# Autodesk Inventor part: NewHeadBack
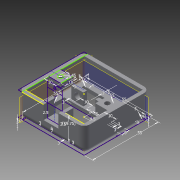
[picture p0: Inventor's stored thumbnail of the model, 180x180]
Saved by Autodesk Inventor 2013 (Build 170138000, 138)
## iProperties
Created: 2013-04
Part Number: NewHeadBack
Material: Generic
Document SubType Name: Modeling
Designer: frankenteddy
Density: 1 g/cm^3
Author: frankenteddy
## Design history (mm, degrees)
node "Blocks"
  sketch "Block1"
    geometry: L1 (49.279, 30.472)-(71.779, 30.472); L2 (71.779, 30.472)-(71.779, 18.072); L3 (71.779, 18.072)-(49.279, 18.072); L4 (49.279, 18.072)-(49.279, 30.472); L5 (49.279, 30.472)-(44.779, 30.472); L6 (44.779, 30.472)-(44.779, 18.072); L7 (44.779, 18.072)-(49.279, 18.072); L8 (49.279, 18.072)-(49.279, 30.472); L9 (71.779, 30.472)-(76.279, 30.472); L10 (76.279, 30.472)-(76.279, 18.072); L11 (76.279, 18.072)-(71.779, 18.072); L12 (71.779, 18.072)-(71.779, 30.472); L13 (44.779, 24.272)-(76.279, 24.272); L14 (60.529, 30.472)-(60.529, 18.072); L15 (47.029, 30.472)-(47.029, 18.072); L16 (74.029, 30.472)-(74.029, 18.072); C1 r 1.1 at (47.029, 24.272); C2 r 1.1 at (74.029, 24.272); 1 further point
    constraints: 32 end point, 8 midpoint, 6 parallel, 3 horizontal, 3 perpendicular, 2 centre point, 2 point on line
    dimensions: "d9" = 22.5 distance of L2.end L3.end; "d10" = 12.4 distance of L1.end L2.end; "d11" = 4.5 distance of L7.end L6.end; "d12" = 4.5 distance of L10.end L11.end; "d13" = 2.2 diameter of C1; "d14" = 2.2 diameter of C2; "d15" = 2.25 distance between parallel lines of L10 L16
sketch "Sketch1"
  geometry: L1 (-27.5, 27.5)-(27.5, 27.5); L2 (27.5, 27.5)-(27.5, -27.5); L3 (27.5, -27.5)-(-27.5, -27.5); L4 (-27.5, -27.5)-(-27.5, 27.5); L5 (-24.5, 24.5)-(24.5, 24.5); L6 (24.5, 24.5)-(24.5, -24.5); L7 (24.5, -24.5)-(-24.5, -24.5); L8 (-24.5, -24.5)-(-24.5, 24.5); L9 (-23.5, 27.5)-(-23.5, -27.5); L10 (-27.5, 23.5)-(27.5, 23.5); L11 (-27.5, 4.5)-(27.5, 4.5); L12 (-5, 4.5)-(-15, 4.5); L13 (-15, 4.5)-(-15, 7.5); L14 (-15, 7.5)-(-5, 7.5); L15 (-5, 7.5)-(-5, 4.5); L16 (5, 4.5)-(15, 4.5); L17 (15, 4.5)-(15, 7.5); L18 (15, 7.5)-(5, 7.5); L19 (5, 7.5)-(5, 4.5); L20 (-24.5, 9)-(24.5, 9); L21 (24.5, 9)-(24.5, 3); L22 (24.5, 3)-(-24.5, 3); L23 (-24.5, 3)-(-24.5, 9); L24 (5, 6)-(15, 6); 5 further points
  constraints: 48 end point, 10 parallel, 10 point on line, 8 perpendicular, 5 horizontal, 4 midpoint, 2 coincident, 1 horizontal alignment, 1 vertical alignment
  dimensions: "d0" = 55 distance of L1.start L1.end; "d2" = 55 distance of L1.end L2.end; "d3" = 3 distance between parallel lines of L5 L1; "d4" = 3 distance between parallel lines of L8 L4; "d5" = 3 distance between parallel lines of L2 L6; "d6" = 3 distance between parallel lines of L3 L7; "d48" = 4 distance between parallel lines of L10 L1; "d49" = 4 distance between parallel lines of L4 L9; "d67" = 4.5 distance from line of L11 point (0, 0); "d68" = 10 distance of L13.end L14.end; "d69" = 3 distance of L12.end L13.end; "d70" = 5 distance from line of L15 point (0, 0); "d71" = 10 distance of L18.end L17.end; "d72" = 3 distance of L17.end L16.end; "d73" = 5 distance from line of L19 point (0, 0); "d74" = 6 distance of L20.end L21.end; "d75" = 3 distance between parallel lines of L24 L20
extrude "Extrusion1" new body sketch "Sketch1" distance "d7" = 19.75; taper "d8" = 0 deg
sketch "Sketch2"
  geometry: L1 (0, 0)-(49, 0) reference; L2 (49, -19.75)-(0, -19.75) reference; L3 (24.5, -19.75)-(24.5, 0); L4 (15.8, 0)-(15.8, -19.75); L5 (33.2, -19.75)-(33.2, 0); L6 (15.8, -19.75)-(33.2, -19.75); L7 (0, 0)-(0, -19.75) reference; L8 (49, 0)-(49, -19.75) reference; L9 (0, -3)-(15.8, -3); L10 (33.2, -3)-(49, -3)
  constraints: 12 end point, 8 point on line, 5 perpendicular, 2 vertical, 1 midpoint
  dimensions: "d16" = 4 dimension on L1; "d17" = 19.75 dimension on L1 (derived); "d18" = 2.5 dimension on L4; "d19" = 2.5 dimension on L5; "d35" = 3 distance between parallel lines of L9 L1; "d36" = 3 distance between parallel lines of L10 L1
  node "Block1:1" dims "d16" = 4, "d17" = 19.75 (derived), "d18" = 2.5, "d19" = 2.5, "d35" = 3, "d36" = 3
extrude "Extrusion2" join sketch "Sketch2" distance "d20" = 7; taper "d21" = 0 deg
extrude "Extrusion3" cut sketch "Sketch2" distance "d22" = 7; taper "d23" = 0 deg
extrude "Extrusion4" cut sketch "Sketch2" distance "d24" = 3; taper "d25" = 0 deg
sketch "Sketch3"
  geometry: L1 (-27.5, -27.5)-(-6.2, -27.5) reference; L2 (-27.5, 27.5)-(-24.5, 27.5); L3 (-24.5, 27.5)-(-24.5, -27.5); L4 (-24.5, -27.5)-(-27.5, -27.5); L5 (-27.5, -27.5)-(-27.5, 27.5); L6 (-27.5, 0)-(0, 0); L7 (-24.5, 5)-(-14.5, 5); L8 (-14.5, 5)-(-14.5, -5); L9 (-14.5, -5)-(-24.5, -5); L10 (-24.5, -5)-(-24.5, 5); L11 (-19.5, 5)-(-19.5, -5); C1 r 2 at (-19.5, 0)
  constraints: 20 end point, 4 midpoint, 4 parallel, 3 perpendicular, 2 horizontal, 2 point on line, 1 centre point
  dimensions: "d26" = 10 distance of L8.end L9.end; "d27" = 10 distance of L7.end L8.end; "d28" = 5 distance between parallel lines of L7 L6; "d29" = 4 diameter of C1
extrude "Extrusion5" join sketch "Sketch3" distance "d30" = 3; taper "d31" = 0 deg
sketch "Sketch4"
  geometry: L1 (24.5, 5)-(14.5, 5); L2 (14.5, 5)-(14.5, -5); L3 (14.5, -5)-(24.5, -5); L4 (24.5, -5)-(24.5, 5); L5 (19.5, 5)-(19.5, -5); L6 (14.5, 0)-(24.5, 0); L7 (19.5, 4.879)-(23.725, 2.439); L8 (23.725, 2.439)-(23.725, -2.439); L9 (23.725, -2.439)-(19.5, -4.879); L10 (19.5, -4.879)-(15.275, -2.439); L11 (15.275, -2.439)-(15.275, 2.439); L12 (15.275, 2.439)-(19.5, 4.879); C1 r 2 at (19.5, 0) reference; 2 further points
  constraints: 24 end point, 4 midpoint, 2 parallel, 1 coincident, 1 horizontal, 1 perpendicular, 1 point on line, 13 other
  dimensions: "d32" = 8.45 distance between parallel lines of L8 L11
extrude "Extrusion6" join sketch "Sketch4" distance "d33" = 3; taper "d34" = 0 deg
extrude "Extrusion7" join sketch "Sketch2" distance "d37" = 5; taper "d38" = 0 deg
sketch "Sketch5"
  geometry: L1 (0, 0)-(-19.75, 0) reference; L2 (0, 49)-(0, 0) reference; L3 (0, 49)-(-19.75, 49) reference; L4 (-3, 49)-(-3, 0); 1 further point
  constraints: 2 end point, 2 point on line, 1 perpendicular
  dimensions: "d39" = 3 distance between parallel lines of L4 L2
extrude "Extrusion8" join sketch "Sketch5" distance "d40" = 5; taper "d41" = 0 deg
sketch "Sketch6"
  geometry: L1 (49, 0)-(0, 0) reference; L2 (49, 0)-(49, 19.75) reference; L3 (0, 0)-(0, 19.75) reference; L4 (0, 3)-(49, 3); 1 further point
  constraints: 2 end point, 2 point on line, 1 perpendicular
  dimensions: "d42" = 3 distance between parallel lines of L4 L1
extrude "Extrusion9" join sketch "Sketch6" distance "d43" = 5; taper "d44" = 0 deg
mirror "Mirror1"
workplane "Work Plane1"
workplane "Work Plane2"
sketch "Sketch7"
  geometry: L1 (0, 0)-(-55, 0) reference; L2 (-55, 0)-(-55, 1); L3 (-55, 1)-(0, 1); L4 (0, 1)-(0, 0) reference; L5 (-4, 1)-(-4, 0); L6 (-51, 1)-(-51, 0); L7 (-27.5, 1)-(-27.5, 0); L8 (-27.5, 3.5)-(-27.5, -1.5); L9 (-4, 3.5)-(-4, -1.5); L10 (-51, 3.5)-(-51, -1.5); A1 r 2.5 centre (-51, 1) between (-51, 3.5) and (-51, -1.5); A2 r 2.5 centre (-4, 1) between (-4, 3.5) and (-4, -1.5); A3 r 2.5 centre (-27.5, 1) between (-27.5, 3.5) and (-27.5, -1.5)
  constraints: 20 end point, 6 point on circle, 4 parallel, 4 point on line, 3 centre point, 3 coincident, 3 perpendicular, 2 horizontal, 1 collinear, 1 midpoint, 1 vertical
  dimensions: "d51" = 55 distance of L2.end L3.end; "d52" = 1 distance of L1.end L2.end; "d53" = 4 distance between parallel lines of L5 L4; "d54" = 4 distance between parallel lines of L2 L6; "d55" = 5 diameter of A1; "d56" = 5 diameter of A2; "d57" = 5 diameter of A3
sketch "Sketch8"
  geometry: L1 (0, 0)-(-55, 0) reference; L2 (-55, 0)-(-55, 1); L3 (-55, 1)-(0, 1); L4 (0, 1)-(0, 0) reference; L5 (-27.5, 1)-(-27.5, 0); L6 (-27.5, 3.5)-(-27.5, -1.5); A1 r 2.5 centre (-27.5, 1) between (-27.5, 3.5) and (-27.5, -1.5)
  constraints: 12 end point, 2 horizontal, 2 parallel, 2 point on circle, 1 centre point, 1 coincident, 1 collinear, 1 midpoint, 1 perpendicular, 1 vertical
  dimensions: "d61" = 55 distance of L2.end L3.end; "d62" = 1 distance of L1.end L2.end; "d63" = 5 diameter of A1
extrude "Extrusion10" cut sketch "Sketch2" distance "d65" = 6; taper "d66" = 0 deg
extrude "Extrusion11" join sketch "Sketch1" distance "d76" = 3; taper "d77" = 0 deg
extrude "Extrusion12" join sketch "Sketch1" distance "d78" = 13; taper "d79" = 0 deg
sketch "Sketch9"
  geometry: C1 r 2.6 at (5, -5); 1 further point
  constraints: 1 centre point
  dimensions: "d80" = 5.2 diameter of C1
sketch "Sketch10"
  geometry: C1 r 2.6 at (5, -5); 1 further point
  constraints: 1 centre point
  dimensions: "d81" = 5.2 diameter of C1
extrude "Extrusion13" cut sketch "Sketch9" distance "d82" = 3; taper "d83" = 0 deg
extrude "Extrusion14" cut sketch "Sketch10" distance "d84" = 3; taper "d85" = 0 deg
fillet "Fillet10" dims "d98" = 3
fillet "Fillet11" dims "d99" = 5
body "Solid1"
